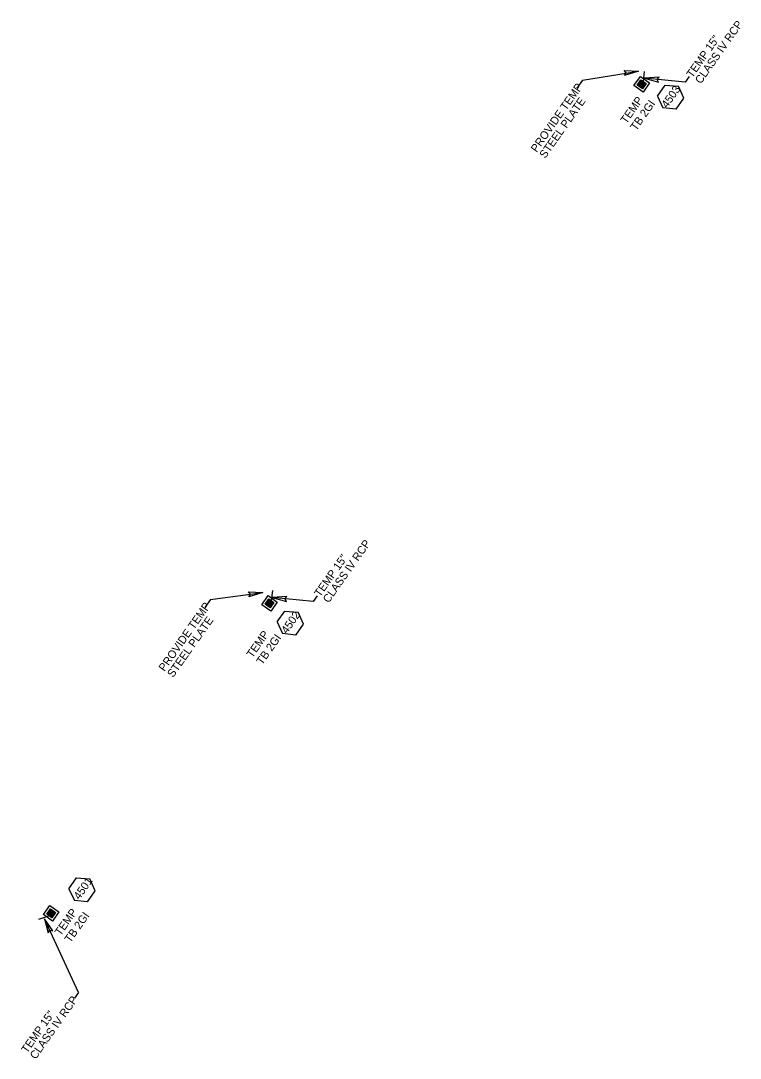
# Model space of a CAD drawing. Extents: x 2214978 to 2238755, y 984122 to 1016255.
# Drawn here: x 2216787 to 2217236, y 986569 to 987217 of the extents above; entities that cross this region are included whole.
import ezdxf

# ---------------------------------------------------------------- set-up
doc = ezdxf.new("R2010")
doc.units = 0
for name, color, linetype in [('Prop Drainage Structure Box Number Symbol CELL', 7, 'Continuous'), ('Prop Drainage Structure Drop Inlet Grate 2 Wide Slots and Sag Grates 840 22 TB CELL', 7, 'Continuous'), ('Prop Drainage Structure Drop Inlet Grate 2 Wide Slots and Sag Grates 840 22 TB Label', 7, 'Continuous'), ('Prop Drainage Structure Pipe Alternate 15in', 7, 'Continuous'), ('Prop Drainage Structure Pipe RCP 15in Class IV', 7, 'Continuous'), ('Prop Drainage Structure Plot Symbol 20 Scale', 7, 'Continuous'), ('Prop Drainage Structure Plot Symbol 50 Scale', 7, 'Continuous'), ('Prop Plan Preparation Drainage Notes Label', 7, 'Continuous')]:
    doc.layers.add(name, color=color, linetype=linetype)

msp = doc.modelspace()

# ---------------------------------------------------------------- linework, layer by layer
at = {"layer": 'Prop Drainage Structure Box Number Symbol CELL'}
for p, q in [((2217184.65, 987169.75), (2217189.48, 987176.61)), ((2217189.48, 987176.61), (2217197.78, 987175.99)), ((2217201.15, 987168.38), (2217197.78, 987175.99)), ((2217184.65, 987169.75), (2217188.16, 987162.47)), ((2217196.31, 987161.52), (2217201.15, 987168.38)), ((2217196.31, 987161.52), (2217188.16, 987162.47)), ((2216946.86, 986841.13), (2216951.7, 986847.99)), ((2216951.7, 986847.99), (2216959.99, 986847.37)), ((2216963.37, 986839.77), (2216959.99, 986847.37)), ((2216946.86, 986841.13), (2216950.38, 986833.86)), ((2216958.53, 986832.9), (2216963.37, 986839.77)), ((2216958.53, 986832.9), (2216950.38, 986833.86)), ((2216816.71, 986674.43), (2216821.54, 986681.29)), ((2216821.54, 986681.29), (2216829.84, 986680.67)), ((2216816.71, 986674.43), (2216820.23, 986667.15)), ((2216833.21, 986673.07), (2216829.84, 986680.67)), ((2216828.37, 986666.2), (2216833.21, 986673.07)), ((2216828.37, 986666.2), (2216820.23, 986667.15))]:
    msp.add_line(p, q, dxfattribs=at)
at = {"layer": 'Prop Drainage Structure Drop Inlet Grate 2 Wide Slots and Sag Grates 840 22 TB CELL'}
for p, q in [((2217173.7, 987175.51), (2217173.7, 987175.51)), ((2217173.9, 987177.82), (2217173.9, 987177.82)), ((2217174.85, 987177.15), (2217174.85, 987177.15)), ((2217175.8, 987176.47), (2217175.8, 987176.47)), ((2217176, 987178.78), (2217176, 987178.78)), ((2216941.01, 986851.09), (2216941.01, 986851.09)), ((2216941.21, 986853.4), (2216941.21, 986853.4)), ((2216942.16, 986852.73), (2216942.16, 986852.73)), ((2216943.12, 986852.06), (2216943.12, 986852.06)), ((2216943.31, 986854.36), (2216943.31, 986854.36)), ((2216804.52, 986657.48), (2216804.52, 986657.48)), ((2216804.72, 986659.79), (2216804.72, 986659.79)), ((2216805.67, 986659.12), (2216805.67, 986659.12)), ((2216806.62, 986658.45), (2216806.62, 986658.45)), ((2216806.82, 986660.75), (2216806.82, 986660.75))]:
    msp.add_line(p, q, dxfattribs=at)
for points in [[(2217176.95, 987178.11), (2217174.65, 987174.84), (2217172.74, 987176.18), (2217175.05, 987179.45), (2217176.95, 987178.11)], [(2217176.87, 987178.09), (2217174.64, 987174.93), (2217172.83, 987176.2), (2217175.06, 987179.37), (2217176.87, 987178.09), (2217176.87, 987178.09)], [(2217175.74, 987176.51), (2217174.63, 987174.94), (2217172.84, 987176.2), (2217173.95, 987177.77), (2217175.74, 987176.51)], [(2217173.75, 987176.69), (2217173.27, 987176), (2217173.05, 987176.16), (2217173.53, 987176.84), (2217173.75, 987176.69)], [(2217174.06, 987176.46), (2217173.58, 987175.78), (2217173.36, 987175.94), (2217173.84, 987176.62), (2217174.06, 987176.46)], [(2217174.28, 987177.44), (2217173.8, 987176.75), (2217173.57, 987176.91), (2217174.05, 987177.59), (2217174.28, 987177.44)], [(2217174.38, 987176.24), (2217173.9, 987175.56), (2217173.68, 987175.72), (2217174.16, 987176.4), (2217174.38, 987176.24)], [(2217174.59, 987177.21), (2217174.11, 987176.53), (2217173.89, 987176.69), (2217174.37, 987177.37), (2217174.59, 987177.21)], [(2217176.85, 987178.09), (2217175.75, 987176.52), (2217173.96, 987177.78), (2217175.07, 987179.35), (2217176.85, 987178.09)], [(2217174.69, 987176.02), (2217174.21, 987175.34), (2217173.99, 987175.49), (2217174.47, 987176.18), (2217174.69, 987176.02)], [(2217174.86, 987178.27), (2217174.38, 987177.59), (2217174.16, 987177.74), (2217174.64, 987178.43), (2217174.86, 987178.27)], [(2217174.91, 987176.99), (2217174.43, 987176.31), (2217174.2, 987176.47), (2217174.68, 987177.15), (2217174.91, 987176.99)], [(2217175.01, 987175.8), (2217174.53, 987175.12), (2217174.31, 987175.27), (2217174.79, 987175.95), (2217175.01, 987175.8)], [(2217175.18, 987178.05), (2217174.7, 987177.37), (2217174.48, 987177.52), (2217174.96, 987178.2), (2217175.18, 987178.05)], [(2217175.22, 987176.77), (2217174.74, 987176.09), (2217174.52, 987176.24), (2217175, 987176.92), (2217175.22, 987176.77)], [(2217175.39, 987179.02), (2217174.91, 987178.34), (2217174.69, 987178.49), (2217175.17, 987179.17), (2217175.39, 987179.02)], [(2217175.49, 987177.83), (2217175.01, 987177.14), (2217174.79, 987177.3), (2217175.27, 987177.98), (2217175.49, 987177.83)], [(2217175.54, 987176.55), (2217175.06, 987175.87), (2217174.83, 987176.02), (2217175.31, 987176.7), (2217175.54, 987176.55)], [(2217175.71, 987178.8), (2217175.23, 987178.12), (2217175.01, 987178.27), (2217175.49, 987178.95), (2217175.71, 987178.8)], [(2217175.81, 987177.6), (2217175.33, 987176.92), (2217175.11, 987177.08), (2217175.59, 987177.76), (2217175.81, 987177.6)], [(2217176.02, 987178.57), (2217175.54, 987177.89), (2217175.32, 987178.05), (2217175.8, 987178.73), (2217176.02, 987178.57)], [(2217176.12, 987177.38), (2217175.64, 987176.7), (2217175.42, 987176.86), (2217175.9, 987177.54), (2217176.12, 987177.38)], [(2217176.34, 987178.35), (2217175.86, 987177.67), (2217175.64, 987177.83), (2217176.12, 987178.51), (2217176.34, 987178.35)], [(2217176.65, 987178.13), (2217176.17, 987177.45), (2217175.95, 987177.61), (2217176.43, 987178.29), (2217176.65, 987178.13)], [(2216944.27, 986853.69), (2216941.96, 986850.42), (2216940.06, 986851.77), (2216942.36, 986855.04), (2216944.27, 986853.69)], [(2216944.18, 986853.68), (2216941.95, 986850.51), (2216940.14, 986851.78), (2216942.38, 986854.95), (2216944.18, 986853.68), (2216944.18, 986853.68)], [(2216943.05, 986852.09), (2216941.95, 986850.52), (2216940.16, 986851.78), (2216941.26, 986853.35), (2216943.05, 986852.09)], [(2216941.06, 986852.27), (2216940.58, 986851.59), (2216940.36, 986851.74), (2216940.84, 986852.43), (2216941.06, 986852.27)], [(2216941.38, 986852.05), (2216940.9, 986851.37), (2216940.67, 986851.52), (2216941.15, 986852.2), (2216941.38, 986852.05)], [(2216941.59, 986853.02), (2216941.11, 986852.34), (2216940.89, 986852.49), (2216941.37, 986853.17), (2216941.59, 986853.02)], [(2216941.69, 986851.83), (2216941.21, 986851.14), (2216940.99, 986851.3), (2216941.47, 986851.98), (2216941.69, 986851.83)], [(2216941.9, 986852.8), (2216941.42, 986852.12), (2216941.2, 986852.27), (2216941.68, 986852.95), (2216941.9, 986852.8)], [(2216944.17, 986853.67), (2216943.06, 986852.11), (2216941.27, 986853.37), (2216942.38, 986854.93), (2216944.17, 986853.67)], [(2216942.01, 986851.6), (2216941.53, 986850.92), (2216941.3, 986851.08), (2216941.78, 986851.76), (2216942.01, 986851.6)], [(2216942.18, 986853.85), (2216941.7, 986853.17), (2216941.48, 986853.33), (2216941.96, 986854.01), (2216942.18, 986853.85)], [(2216942.22, 986852.57), (2216941.74, 986851.89), (2216941.52, 986852.05), (2216942, 986852.73), (2216942.22, 986852.57)], [(2216942.32, 986851.38), (2216941.84, 986850.7), (2216941.62, 986850.86), (2216942.1, 986851.54), (2216942.32, 986851.38)], [(2216942.49, 986853.63), (2216942.01, 986852.95), (2216941.79, 986853.11), (2216942.27, 986853.79), (2216942.49, 986853.63)], [(2216942.53, 986852.35), (2216942.05, 986851.67), (2216941.83, 986851.83), (2216942.31, 986852.51), (2216942.53, 986852.35)], [(2216942.71, 986854.6), (2216942.23, 986853.92), (2216942, 986854.08), (2216942.48, 986854.76), (2216942.71, 986854.6)], [(2216942.81, 986853.41), (2216942.33, 986852.73), (2216942.11, 986852.88), (2216942.59, 986853.57), (2216942.81, 986853.41)], [(2216942.85, 986852.13), (2216942.37, 986851.45), (2216942.15, 986851.61), (2216942.63, 986852.29), (2216942.85, 986852.13)], [(2216943.02, 986854.38), (2216942.54, 986853.7), (2216942.32, 986853.86), (2216942.8, 986854.54), (2216943.02, 986854.38)], [(2216943.12, 986853.19), (2216942.64, 986852.51), (2216942.42, 986852.66), (2216942.9, 986853.34), (2216943.12, 986853.19)], [(2216943.34, 986854.16), (2216942.86, 986853.48), (2216942.63, 986853.63), (2216943.11, 986854.31), (2216943.34, 986854.16)], [(2216943.44, 986852.97), (2216942.96, 986852.28), (2216942.74, 986852.44), (2216943.22, 986853.12), (2216943.44, 986852.97)], [(2216943.65, 986853.94), (2216943.17, 986853.26), (2216942.95, 986853.41), (2216943.43, 986854.09), (2216943.65, 986853.94)], [(2216943.97, 986853.71), (2216943.49, 986853.03), (2216943.26, 986853.19), (2216943.74, 986853.87), (2216943.97, 986853.71)], [(2216803.56, 986658.16), (2216805.87, 986661.43), (2216807.78, 986660.08), (2216805.47, 986656.81), (2216803.56, 986658.16)], [(2216803.65, 986658.17), (2216805.88, 986661.34), (2216807.69, 986660.07), (2216805.46, 986656.9), (2216803.65, 986658.17), (2216803.65, 986658.17)], [(2216803.67, 986658.17), (2216804.77, 986659.74), (2216806.56, 986658.48), (2216805.45, 986656.91), (2216803.67, 986658.17)], [(2216803.87, 986658.13), (2216804.35, 986658.81), (2216804.57, 986658.66), (2216804.09, 986657.98), (2216803.87, 986658.13)], [(2216804.18, 986657.91), (2216804.66, 986658.59), (2216804.88, 986658.44), (2216804.4, 986657.76), (2216804.18, 986657.91)], [(2216804.4, 986658.88), (2216804.88, 986659.56), (2216805.1, 986659.41), (2216804.62, 986658.73), (2216804.4, 986658.88)], [(2216804.5, 986657.69), (2216804.98, 986658.37), (2216805.2, 986658.21), (2216804.72, 986657.53), (2216804.5, 986657.69)], [(2216804.71, 986658.66), (2216805.19, 986659.34), (2216805.41, 986659.19), (2216804.93, 986658.5), (2216804.71, 986658.66)], [(2216804.78, 986659.76), (2216805.89, 986661.32), (2216807.67, 986660.06), (2216806.57, 986658.5), (2216804.78, 986659.76)], [(2216804.81, 986657.47), (2216805.29, 986658.15), (2216805.51, 986657.99), (2216805.03, 986657.31), (2216804.81, 986657.47)], [(2216804.98, 986659.72), (2216805.46, 986660.4), (2216805.69, 986660.24), (2216805.21, 986659.56), (2216804.98, 986659.72)], [(2216805.03, 986658.44), (2216805.51, 986659.12), (2216805.73, 986658.96), (2216805.25, 986658.28), (2216805.03, 986658.44)], [(2216805.13, 986657.25), (2216805.61, 986657.93), (2216805.83, 986657.77), (2216805.35, 986657.09), (2216805.13, 986657.25)], [(2216805.3, 986659.5), (2216805.78, 986660.18), (2216806, 986660.02), (2216805.52, 986659.34), (2216805.3, 986659.5)], [(2216805.34, 986658.22), (2216805.82, 986658.9), (2216806.04, 986658.74), (2216805.56, 986658.06), (2216805.34, 986658.22)], [(2216805.51, 986660.47), (2216805.99, 986661.15), (2216806.21, 986660.99), (2216805.73, 986660.31), (2216805.51, 986660.47)], [(2216805.61, 986659.27), (2216806.09, 986659.95), (2216806.32, 986659.8), (2216805.84, 986659.12), (2216805.61, 986659.27)], [(2216805.66, 986657.99), (2216806.14, 986658.68), (2216806.36, 986658.52), (2216805.88, 986657.84), (2216805.66, 986657.99)], [(2216805.83, 986660.24), (2216806.31, 986660.93), (2216806.53, 986660.77), (2216806.05, 986660.09), (2216805.83, 986660.24)], [(2216805.93, 986659.05), (2216806.41, 986659.73), (2216806.63, 986659.58), (2216806.15, 986658.9), (2216805.93, 986659.05)], [(2216806.14, 986660.02), (2216806.62, 986660.7), (2216806.84, 986660.55), (2216806.36, 986659.87), (2216806.14, 986660.02)], [(2216806.24, 986658.83), (2216806.72, 986659.51), (2216806.95, 986659.35), (2216806.47, 986658.67), (2216806.24, 986658.83)], [(2216806.46, 986659.8), (2216806.94, 986660.48), (2216807.16, 986660.33), (2216806.68, 986659.64), (2216806.46, 986659.8)], [(2216806.77, 986659.58), (2216807.25, 986660.26), (2216807.47, 986660.1), (2216806.99, 986659.42), (2216806.77, 986659.58)]]:
    msp.add_lwpolyline(points, dxfattribs=at)
at = {"layer": 'Prop Drainage Structure Pipe Alternate 15in'}
for p, q in [((2217176, 987178.78), (2217176.69, 987185.13)), ((2216804.52, 986657.48), (2216797.79, 986655.14))]:
    msp.add_line(p, q, dxfattribs=at)
at = {"layer": 'Prop Drainage Structure Pipe RCP 15in Class IV'}
msp.add_line((2216944, 986860.71), (2216943.31, 986854.36), dxfattribs=at)
at = {"layer": 'Prop Drainage Structure Plot Symbol 20 Scale'}
for points in [[(2217177.64, 987177.63), (2217175.33, 987174.36), (2217172.06, 987176.66), (2217174.37, 987179.93)], [(2216944.95, 986853.21), (2216942.64, 986849.94), (2216939.38, 986852.25), (2216941.68, 986855.52)], [(2216802.88, 986658.64), (2216805.19, 986661.91), (2216808.46, 986659.6), (2216806.15, 986656.33)]]:
    msp.add_lwpolyline(points, close=True, dxfattribs=at)
at = {"layer": 'Prop Drainage Structure Plot Symbol 50 Scale'}
for points in [[(2217179.73, 987177.99), (2217175.69, 987172.27), (2217169.97, 987176.3), (2217174.01, 987182.02)], [(2216947.04, 986853.57), (2216943.01, 986847.85), (2216937.28, 986851.89), (2216941.32, 986857.61)], [(2216800.79, 986658.27), (2216804.83, 986664), (2216810.55, 986659.96), (2216806.51, 986654.24)]]:
    msp.add_lwpolyline(points, close=True, dxfattribs=at)
at = {"layer": 'Prop Plan Preparation Drainage Notes Label'}
for p, q in [((2217137.93, 987179.66), (2217172.95, 987185.32)), ((2217202.08, 987178.4), (2217176.58, 987180.92)), ((2217204.56, 987181.91), (2217202.08, 987178.4)), ((2217137.93, 987179.66), (2217134.38, 987174.62)), ((2216905.25, 986855.25), (2216938.02, 986859.63)), ((2216969.4, 986853.98), (2216943.89, 986856.51)), ((2216971.87, 986857.49), (2216969.4, 986853.98)), ((2216905.25, 986855.25), (2216901.69, 986850.2)), ((2216822.79, 986609.66), (2216801.54, 986655.67)), ((2216822.79, 986609.66), (2216820.32, 986606.15))]:
    msp.add_line(p, q, dxfattribs=at)
for points in [[(2217163.82, 987185.66), (2217172.95, 987185.32), (2217164.19, 987182.53), (2217165.12, 987184.27)], [(2217185.69, 987181.58), (2217176.58, 987180.92), (2217185.43, 987178.44), (2217184.44, 987180.15)], [(2216928.89, 986859.98), (2216938.02, 986859.63), (2216929.26, 986856.85), (2216930.19, 986858.59)], [(2216953, 986857.16), (2216943.89, 986856.51), (2216952.74, 986854.02), (2216951.75, 986855.73)], [(2216806.72, 986648.15), (2216801.54, 986655.67), (2216803.88, 986646.79), (2216804.85, 986648.5)]]:
    msp.add_lwpolyline(points, close=True, dxfattribs=at)

# ---------------------------------------------------------------- texts
at = {"layer": 'Prop Drainage Structure Box Number Symbol CELL'}
for s, p in [('4503', (2217190.81, 987161.92)), ('4502', (2216953.11, 986833.42)), ('4501', (2216823.33, 986667.24))]:
    msp.add_text(s, height=5, rotation=54.81679, dxfattribs=at).set_placement(p)
at = {"layer": 'Prop Drainage Structure Drop Inlet Grate 2 Wide Slots and Sag Grates 840 22 TB Label'}
for s, p in [('TEMP', (2217165.27, 987152.05)), ('TB 2GI', (2217171.4, 987147.73)), ('TEMP', (2216931.48, 986818.26)), ('TB 2GI', (2216937.61, 986813.94)), ('TEMP', (2216811.55, 986644.63)), ('TB 2GI', (2216817.68, 986640.3))]:
    msp.add_text(s, height=5, rotation=54.81679, dxfattribs=at).set_placement(p)
at = {"layer": 'Prop Plan Preparation Drainage Notes Label'}
for s, rotation, p in [('CLASS IV RCP', 54.87318, (2217211.86, 987177.03)), ('TEMP 15"', 54.87318, (2217206.5, 987180.8)), ('PROVIDE TEMP', 54.83068, (2217109.2, 987134.24)), ('STEEL PLATE', 54.83068, (2217114.56, 987130.47)), ('CLASS IV RCP', 54.87318, (2216979.18, 986852.61)), ('TEMP 15"', 54.87318, (2216973.82, 986856.38)), ('PROVIDE TEMP', 54.83068, (2216876.51, 986809.83)), ('STEEL PLATE', 54.83068, (2216881.87, 986806.05)), ('CLASS IV RCP', 54.87318, (2216796.01, 986567.47)), ('TEMP 15"', 54.87318, (2216790.65, 986571.25))]:
    msp.add_text(s, height=5, rotation=rotation, dxfattribs=at).set_placement(p)

doc.saveas('drawing.dxf')
